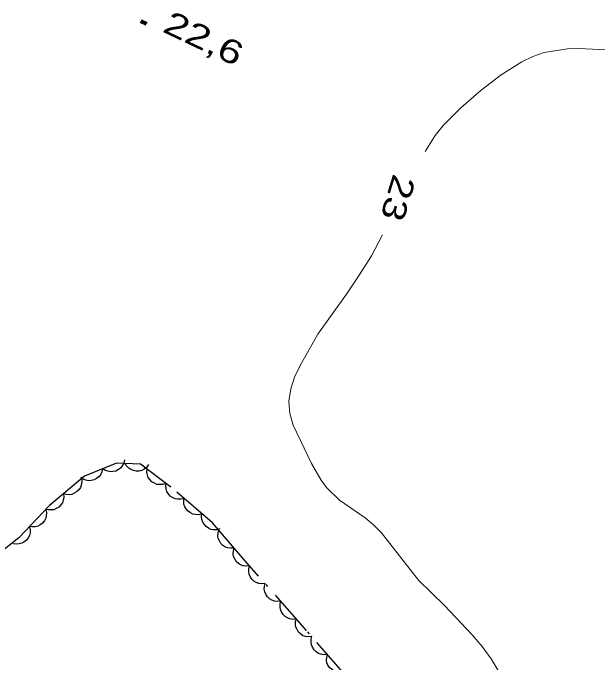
# Model space of a CAD drawing. Extents: x 356765 to 358572, y 5103174 to 5104650.
# Drawn here: x 357122.99 to 357160.15, y 5103993.18 to 5104034.49 of the extents above; entities that cross this region are included whole.
import ezdxf
from ezdxf.enums import TextEntityAlignment as Align

# ---------------------------------------------------------------- set-up
doc = ezdxf.new("R2010")
doc.units = 0
doc.header["$LTSCALE"] = 0.6
doc.linetypes.add('DOT_DASHED', pattern=[7.7, 5, -1.2, 0.3, -1.2])
for name, color, linetype, lineweight in [('2', 7, 'Continuous', 13), ('3', 7, 'Continuous', 140), ('44', 7, 'Continuous', 25)]:
    doc.layers.add(name, color=color, linetype=linetype, lineweight=lineweight)

msp = doc.modelspace()

# ---------------------------------------------------------------- linework, layer by layer
at = {"layer": '2'}
for points in [[(357149.22, 5104025.67), (357149.85, 5104026.7), (357150.35, 5104027.33), (357151.48, 5104028.45), (357152.77, 5104029.58), (357154.05, 5104030.55), (357155.36, 5104031.38), (357156.06, 5104031.72), (357156.79, 5104031.98), (357158.26, 5104032.22), (357158.97, 5104032.24), (357161.22, 5104032.12)], [(357155.79, 5103989.43), (357153.41, 5103993.38), (357152.84, 5103994.17), (357152.21, 5103994.92), (357150.44, 5103996.79), (357148.78, 5103998.4), (357146.43, 5104001.4), (357145.92, 5104001.92), (357145.39, 5104002.37), (357143.77, 5104003.49), (357142.94, 5104004.29), (357142.6, 5104004.76), (357141.98, 5104005.82), (357140.81, 5104008.26), (357140.6, 5104009.01), (357140.54, 5104009.78), (357140.66, 5104010.57), (357140.91, 5104011.32), (357141.26, 5104012.05), (357142.38, 5104014.05), (357144.2, 5104016.59), (357145.01, 5104017.8), (357145.79, 5104019.04), (357146.49, 5104020.37)]]:
    msp.add_lwpolyline(points, dxfattribs=at)
at = {"layer": '3'}
msp.add_line((357131.13, 5104033.96), (357131.49, 5104033.79), dxfattribs=at)
at = {"layer": '44', "linetype": 'DOT_DASHED'}
msp.add_lwpolyline([(357144.3, 5103992.17), (357141.67, 5103995.19), (357137.59, 5103999.82), (357135.69, 5104002.04), (357133.03, 5104004.31), (357131.1, 5104005.77), (357129.57, 5104005.84), (357127.54, 5104005.02), (357125.31, 5104003.14), (357123.37, 5104001.09), (357121.31, 5103999.51)], dxfattribs=at)
at = {"layer": '44'}
for points in [[(357130.08, 5104006.05), (357130.04, 5104005.84), (357129.94, 5104005.67), (357129.84, 5104005.53), (357129.7, 5104005.43), (357129.54, 5104005.34), (357129.35, 5104005.3), (357129.19, 5104005.28), (357129.02, 5104005.32), (357128.84, 5104005.39), (357128.69, 5104005.49)], [(357131.62, 5104005.75), (357131.5, 5104005.58), (357131.33, 5104005.46), (357131.19, 5104005.38), (357131.02, 5104005.34), (357130.83, 5104005.33), (357130.65, 5104005.37), (357130.49, 5104005.43), (357130.35, 5104005.53), (357130.22, 5104005.66), (357130.12, 5104005.81)], [(357128.69, 5104005.49), (357128.65, 5104005.28), (357128.55, 5104005.1), (357128.45, 5104004.97), (357128.31, 5104004.87), (357128.15, 5104004.78), (357127.96, 5104004.74), (357127.8, 5104004.72), (357127.63, 5104004.76), (357127.45, 5104004.82), (357127.3, 5104004.92)], [(357132.71, 5104004.55), (357132.52, 5104004.48), (357132.31, 5104004.48), (357132.15, 5104004.49), (357131.99, 5104004.56), (357131.83, 5104004.66), (357131.7, 5104004.8), (357131.6, 5104004.93), (357131.54, 5104005.09), (357131.51, 5104005.27), (357131.52, 5104005.45)], [(357127.34, 5104004.86), (357127.37, 5104004.65), (357127.33, 5104004.45), (357127.28, 5104004.29), (357127.17, 5104004.15), (357127.04, 5104004.02), (357126.88, 5104003.92), (357126.73, 5104003.85), (357126.56, 5104003.83), (357126.37, 5104003.84), (357126.2, 5104003.89)], [(357133.87, 5104003.59), (357133.67, 5104003.54), (357133.46, 5104003.54), (357133.3, 5104003.57), (357133.14, 5104003.65), (357132.99, 5104003.75), (357132.87, 5104003.9), (357132.78, 5104004.04), (357132.73, 5104004.2), (357132.71, 5104004.39), (357132.73, 5104004.57)], [(357126.2, 5104003.89), (357126.22, 5104003.68), (357126.18, 5104003.48), (357126.13, 5104003.32), (357126.03, 5104003.18), (357125.9, 5104003.05), (357125.73, 5104002.95), (357125.58, 5104002.88), (357125.41, 5104002.86), (357125.22, 5104002.87), (357125.05, 5104002.92)], [(357135.01, 5104002.62), (357134.81, 5104002.56), (357134.61, 5104002.57), (357134.44, 5104002.6), (357134.28, 5104002.67), (357134.13, 5104002.78), (357134.01, 5104002.93), (357133.92, 5104003.06), (357133.87, 5104003.23), (357133.85, 5104003.41), (357133.87, 5104003.59)], [(357125.08, 5104002.89), (357125.12, 5104002.69), (357125.11, 5104002.49), (357125.07, 5104002.33), (357124.99, 5104002.17), (357124.87, 5104002.03), (357124.72, 5104001.91), (357124.58, 5104001.83), (357124.41, 5104001.79), (357124.22, 5104001.78), (357124.05, 5104001.8)], [(357136.15, 5104001.65), (357135.95, 5104001.59), (357135.75, 5104001.6), (357135.58, 5104001.62), (357135.43, 5104001.7), (357135.27, 5104001.81), (357135.15, 5104001.95), (357135.06, 5104002.09), (357135.01, 5104002.26), (357134.99, 5104002.44), (357135.01, 5104002.62)], [(357124.05, 5104001.8), (357124.09, 5104001.6), (357124.08, 5104001.4), (357124.04, 5104001.24), (357123.96, 5104001.08), (357123.84, 5104000.94), (357123.69, 5104000.82), (357123.55, 5104000.74), (357123.38, 5104000.7), (357123.19, 5104000.69), (357123.01, 5104000.71)], [(357137.06, 5104000.44), (357136.85, 5104000.42), (357136.65, 5104000.45), (357136.5, 5104000.5), (357136.35, 5104000.6), (357136.22, 5104000.73), (357136.12, 5104000.9), (357136.05, 5104001.05), (357136.03, 5104001.22), (357136.04, 5104001.41), (357136.08, 5104001.58)], [(357138.03, 5103999.3), (357137.83, 5103999.28), (357137.63, 5103999.31), (357137.47, 5103999.36), (357137.33, 5103999.46), (357137.19, 5103999.59), (357137.1, 5103999.76), (357137.03, 5103999.91), (357137, 5104000.08), (357137.01, 5104000.27), (357137.06, 5104000.44)], [(357139.03, 5103998.18), (357138.83, 5103998.15), (357138.63, 5103998.19), (357138.47, 5103998.24), (357138.32, 5103998.34), (357138.19, 5103998.46), (357138.09, 5103998.63), (357138.02, 5103998.77), (357137.99, 5103998.95), (357138, 5103999.13), (357138.04, 5103999.31)], [(357140.03, 5103997.06), (357139.82, 5103997.03), (357139.62, 5103997.06), (357139.46, 5103997.11), (357139.31, 5103997.21), (357139.18, 5103997.34), (357139.08, 5103997.5), (357139.01, 5103997.65), (357138.98, 5103997.82), (357138.99, 5103998.01), (357139.03, 5103998.18)], [(357141.02, 5103995.93), (357140.81, 5103995.9), (357140.61, 5103995.94), (357140.45, 5103995.99), (357140.31, 5103996.08), (357140.17, 5103996.21), (357140.07, 5103996.37), (357140, 5103996.52), (357139.98, 5103996.7), (357139.98, 5103996.88), (357140.03, 5103997.06)], [(357142.01, 5103994.8), (357141.8, 5103994.78), (357141.6, 5103994.81), (357141.44, 5103994.86), (357141.3, 5103994.96), (357141.16, 5103995.09), (357141.06, 5103995.25), (357140.99, 5103995.4), (357140.97, 5103995.57), (357140.97, 5103995.76), (357141.02, 5103995.93)], [(357142.99, 5103993.67), (357142.78, 5103993.65), (357142.58, 5103993.68), (357142.43, 5103993.73), (357142.28, 5103993.83), (357142.15, 5103993.96), (357142.05, 5103994.12), (357141.98, 5103994.27), (357141.96, 5103994.44), (357141.96, 5103994.63), (357142.01, 5103994.8)], [(357143.98, 5103992.54), (357143.77, 5103992.52), (357143.57, 5103992.55), (357143.41, 5103992.6), (357143.27, 5103992.7), (357143.13, 5103992.83), (357143.03, 5103992.99), (357142.96, 5103993.14), (357142.94, 5103993.31), (357142.95, 5103993.5), (357142.99, 5103993.67)]]:
    msp.add_lwpolyline(points, dxfattribs=at)

# ---------------------------------------------------------------- texts
at = {"layer": '2', "width": 1.3}
msp.add_text('23', height=1.5, rotation=253.057, dxfattribs=at).set_placement((357146.7761, 5104022.9286), align=Align.CENTER)
at = {"layer": '3', "width": 1.35}
msp.add_text('22,6   ', height=1.5, rotation=334.619, dxfattribs=at).set_placement((357132.43, 5104033.33))

doc.saveas('drawing.dxf')
